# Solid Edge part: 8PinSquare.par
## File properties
Author: conerly
Template: ansi part.par
Last saved by: jccrumbl
Revision: 23
Application: Solid Edge
Density: 0.03699434701 lbm/in^3
Accuracy: 0.990
Material: ABS Plastic, high impact
Face Style: Red
Fill Style: ANSI34(Plastic)
Virtual Style: Red (Shiny)
Coef. of Thermal Exp: 9e-05
Thermal Conductivity: 0.2
Specific Heat: 0.0
Modulus of Elasticity: 1378951400.0
Poisson's Ratio: 0.4
Yield Stress: 31026406.5
Ultimate Stress: 0.0
Elongation: 0.0
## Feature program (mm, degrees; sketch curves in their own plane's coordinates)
sketch for "unnamed Protrusion 1" plane through (0, 0, 0) normal (0, -1, 0) x-axis (1, 0, 0)
  line (-12.7, -6.35) -> (12.7, -6.35)
  line (12.7, -6.35) -> (12.7, 6.35)
  line (12.7, 6.35) -> (-12.7, 6.35)
  line (-12.7, 6.35) -> (-12.7, -6.35)
  dimension (linear) = 12.7
  dimension (linear) = 12.7
extrude "unnamed Protrusion 1" add finite 25.4 along -normal
sketch for "ExtrudedCutout_1" plane through (0, 0, 0) normal (0, -1, 0) x-axis (1, 0, 0)
  circle centre (-10.16, 3.81) radius 1.0489
extrude "ExtrudedCutout_1" cut finite 1.27 along -normal
pattern "unnamed Pattern 1" of "ExtrudedCutout_1"
extrude "unnamed Cutout 1" cut finite 1.27
extrude "unnamed Cutout 2" cut finite 1.27
extrude "unnamed Cutout 3" cut finite 1.27
extrude "unnamed Cutout 4" cut finite 1.27
extrude "unnamed Cutout 5" cut finite 1.27
extrude "unnamed Cutout 6" cut finite 1.27
extrude "unnamed Cutout 7" cut finite 1.27
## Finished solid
Body 1: solid body, 22 faces, 28 edges, 8 vertices.
  Faces by surface: plane 14, cylinder 8
  Edges by curve: circle 16, line 12
Bounding box of the edges (mm): 25.400 x 25.400 x 12.700, from (-12.7, 0, -6.35) to (12.7, 25.4, 6.35).
Cylindrical faces by radius (mm): R1.0489 x8
Planar faces by outward normal: +x 1, +y 1, +z 1, -x 1, -y 9, -z 1
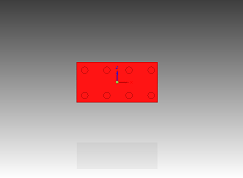
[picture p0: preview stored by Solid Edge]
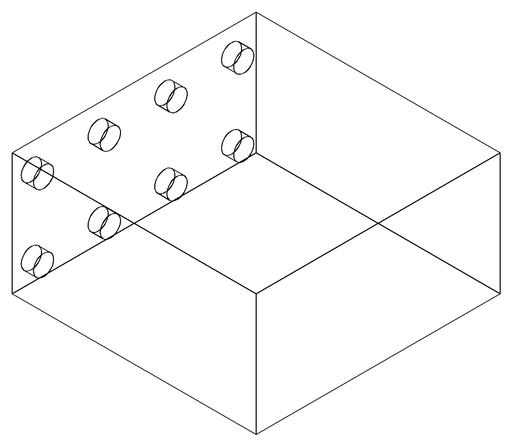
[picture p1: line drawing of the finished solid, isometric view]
